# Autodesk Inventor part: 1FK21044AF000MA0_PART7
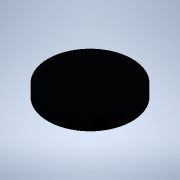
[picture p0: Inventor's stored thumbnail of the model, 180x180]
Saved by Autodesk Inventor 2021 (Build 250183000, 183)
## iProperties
Created: 2025-04
Part Number: 1FK21044AF000MA0_PART7
Material: Generic
Catalog Web Link: www.3dfindit.com
Description: -Servo synchronous motor
Document SubType Name: Modeling
Designer: psAdmin
Mass: 0.299142 g
Surface Area: 3.8585 cm^2
Volume: 0.299142 cm^3
Density: 1 g/cm^3
Appearance: PSOLRGB-38-46-56
Category: PARTsolutions
Title: 1FK21044AF000MA0_PART7
Author: Cadenas PARTsolutions
Comments: Servo synchronous motor
Sending System: PARTsolutions
Preprocessor: ST-DEVELOPER v19.3
PSOL_IDENT_0: {$CADENAS_DATA/23d-libs/siemens_ag/_cat_/39/c4/1fk21044af000ma0.prj},213 {VTYP=3D},{NB=1FK21044AF000
PSOL_IDENT_1: MA0_PART7},{LINA=1FK21044AF000MA0_PART7},{NN=1FK21044AF000MA0_PART7},{NOPRJ=TRUE},{DATE=19.08.2025 1
PSOL_IDENT_2: 4:00:33},{GEOMDATE=30.07.2025 02:02:22},{VERSION=},{LINEID=10},{WBVAR=},{WBNUMERIC=}  {NB=1FK21044AF
PSOL_IDENT_3: 000MA0_PART7},{LINA=1FK21044AF000MA0_PART7},{KT=DUMMY},{PREVIEW=../../../_pool_/cb/72/p_d211_xx_0043
PSOL_IDENT_4: 4j.png},{DESCSHORT=SIMOTICS S-1FK2 HD, SINAMICS S210 3AC 400V-480V, 1.27 Nm, 3000 rpm},{DESCLONG=SIM
PSOL_IDENT_5: OTICS S-1FK2 HD servo motor M0=1.27 Nm; PN = 0.4 kW at nN=3000 rpm (380-480 V); PN = 0.2 kW at nN=15
PSOL_IDENT_6: 00 rpm (200-240 V); degree of protection IP64; cylindrical shaft D19x40mm; absolute encoder 22-bit +
PSOL_IDENT_7: 12-bit multiturn (encoder AM22DQC); with OCC interface; plug size M17, rotatable; SIMOTICS S-1FK2 s
PSOL_IDENT_8: ervomotorfor a wide range of uses in industrial environments. SIMOTICS S‑1FK2 servomotors are compac
PSOL_IDENT_9: t synchronous motors with a high dynamic performance that set themselves apart as a result of their
PSOL_IDENT_10: high power density, degree of protection and overload capability. The motors are available in two va
PSOL_IDENT_11: riants: as High Dynamic variant (highest dynamic performance as a result of the low intrinsic moment
PSOL_IDENT_12: of inertia for applications demanding a high dynamic performance with low moved masses) - and as Co
PSOL_IDENT_13: mpact variant (precise and stable closed-loop control for medium up to large moved masses as a resul
PSOL_IDENT_14: t of a medium intrinsic moment of inertia). SIMOTICSS‑1FK2 servomotors fully exploit their strengths
PSOL_IDENT_15: in a system with the SINAMICSS210 frequency converter and simple connection using the one cable con
PSOL_IDENT_16: nection (OCC). Advantages include the short control and positioning times, fast and precise correcti
PSOL_IDENT_17: on of disturbing quantities as well as stable control with a high dynamic performance. The servo mot
PSOL_IDENT_18: ors can be configured to address a wide range of requirements. For example with and without holding
PSOL_IDENT_19: brake, IP64 or IP65 degree of protection, singleturn or multiturn absolute encoders - to name just a
PSOL_IDENT_20: few. Further, the servomotors are available in different shaft heights extending from 20 to 100. A
PSOL_IDENT_21: shaft sealing ring is available to achieve an IP65 degree of protection and for subsequent mounting
PSOL_IDENT_22: at the motor or as spare part. SIMOTICS - the optimum motor for each and every motion control applic
PSOL_IDENT_23: ation.},{INTNO=804766906428},{SUPPLIERALTNO=1FK2104-4AF00-0MA0},{MANUID=1FK21044AF000MA0},{MANUNAME=
PSOL_IDENT_24: Siemens},{MANUTYPEDESC=Synchronous motor 1FK2-HD 1.27 NM},{AAU732=SIMOTICS},{AAO057=S-1FK2},{AAU734=
PSOL_IDENT_25: SIMOTICS S-1FK2 HD servo motor M0=1.27 Nm; PN = 0.4 kW at nN=3000 rpm (380-480 V); PN = 0.2 kW at nN=
PSOL_IDENT_26: 1500 rpm (200-240 V); degree of protection IP64; cylindrical shaft D19x40mm; absolute encoder 22-bit
PSOL_IDENT_27: + 12-bit multiturn (encoder AM22DQC); with OCC interface; plug size M17, rotatable;},{AAW338=Synchr
PSOL_IDENT_28: onous motor 1FK2-HD 1.27 NM},{AAO742=SIMOTICS},{AAO663=4042948693322},{NOCUPEROU=1},{PRICEQUANTITY=1
PSOL_IDENT_29: },{QUANTITYMIN=1},{QUANTITYINT=1},{CTN=85015100},{COO=DE},{AAO676=1FK2104-4AF00-0MA0},{AAO677=Siemen
PSOL_IDENT_30: s AG},{ORDERUNIT=C62},{CONTENTUNIT=C62}
NB: 1FK21044AF000MA0_PART7
NT: Servo synchronous motor
NBSYN: $MANUID._PART7
LINA: 1FK21044AF000MA0_PART7
CATALOG: SIEMENS
PREVIEW: ../../../_pool_/cb/72/p_d211_xx_00434j.png
DESCSHORT: SIMOTICS S-1FK2 HD, SINAMICS S210 3AC 400V-480V, 1.27 Nm, 3000 rpm
DESCLONG: SIMOTICS S-1FK2 HD servo motor M0=1.27 Nm; PN = 0.4 kW at nN=3000 rpm (380-480 V); PN = 0.2 kW at nN=1500 rpm (200-240 V); degree of protection IP64; cylindrica
INTNO: 804766906428
SUPPLIERALTNO: 1FK2104-4AF00-0MA0
MANUID: 1FK21044AF000MA0
MANUNAME: Siemens
MANUTYPEDESC: Synchronous motor 1FK2-HD 1.27 NM
AAU732: SIMOTICS
AAO057: S-1FK2
AAU734: SIMOTICS S-1FK2 HD servo motor M0=1.27 Nm; PN = 0.4 kW at nN=3000 rpm (380-480 V); PN = 0.2 kW at nN=1500 rpm (200-240 V); degree of protection IP64; cylindrica
AAW338: Synchronous motor 1FK2-HD 1.27 NM
AAO742: SIMOTICS
AAO663: 4042948693322.0
NOCUPEROU: 1
PRICEQUANTITY: 1
QUANTITYMIN: 1
QUANTITYINT: 1
CTN: 85015100
COO: DE
ARTICLENO: 1FK21044AF000MA0_PART7
BOMINFO: 1FK21044AF000MA0_PART7
CREATOR: CADENAS GmbH
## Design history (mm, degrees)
feature "2025_04_17_15_01_28_0007"
body "Solid1"
